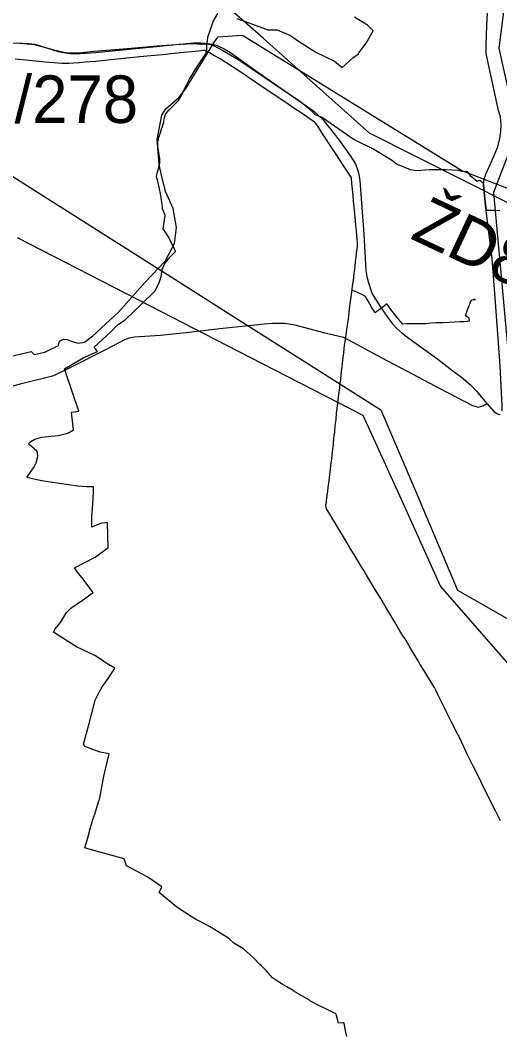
# Model space of a CAD drawing. Extents: x -789162 to -606354, y -1062736 to -945481.
# Drawn here: x -688950 to -687435, y -987160 to -983958 of the extents above; entities that cross this region are included whole.
import ezdxf

# ---------------------------------------------------------------- set-up
doc = ezdxf.new("R2010")
doc.units = 0
for name, color, linetype in [('_Hranice řešeného území', 7, 'Continuous'), ('_SIRSI VZTAHY_CYKLOTRASY MISTNI S', 7, 'Continuous'), ('_SIRSI VZTAHY_ELEKTRICKE VEDENI VN 220 kV S', 7, 'Continuous'), ('_SIRSI VZTAHY_ELEKTRICKE VEDENI VN 400 kV N', 7, 'Continuous'), ('_SIRSI VZTAHY_PRIRODNIHO PARKU', 7, 'Continuous'), ('_SIRSI VZTAHY_SILNICE I a II TRIDY_STAV POPIS', 7, 'Continuous'), ('_SIRSI VZTAHY_SILNICE II TRIDY_STAV', 7, 'Continuous'), ('_SIRSI VZTAHY_SILNICE III TRIDY_STAV', 7, 'Continuous'), ('_SIRSI VZTAHY_USES_RBK_S', 7, 'Continuous'), ('_SIRSI VZTAHY_VTL PLYNOVOD', 7, 'Continuous'), ('_SIRSI VZTAHY_ZELEZNICE NAVRH', 7, 'Continuous'), ('_SIRSI VZTAHY_ZELEZNICE_NAVRH POPIS', 7, 'Continuous')]:
    doc.layers.add(name, color=color, linetype=linetype)

msp = doc.modelspace()

# ---------------------------------------------------------------- linework, layer by layer
at = {"layer": '_Hranice řešeného území'}
for points in [[(-687918.5, -987164.8), (-687923, -987142.5), (-687926.6, -987121.8), (-687928.4, -987122), (-687932.4, -987122.4), (-687944.1, -987123.5), (-687952.2, -987095.3), (-687952.8, -987093.5), (-687982.2, -987078.9), (-688004.2, -987068), (-688032.6, -987053.2), (-688036.5, -987050.9), (-688082.3, -987023.7), (-688087.9, -987020.4), (-688108.1, -987008.6), (-688115.4, -987004.2), (-688122.5, -987000.1), (-688137.5, -986990.9), (-688146.9, -986984.3), (-688153.2, -986979.8), (-688160, -986972.1), (-688172.5, -986957.9), (-688189.3, -986941.5), (-688193, -986937.5), (-688212.3, -986918.4), (-688245.1, -986889), (-688275, -986870.6), (-688289.1, -986858.3), (-688297.7, -986851.7), (-688352.5, -986818.5), (-688363.2, -986811.5), (-688379, -986803.6), (-688396.3, -986794.8), (-688406.4, -986788.3), (-688455.2, -986756.8), (-688511.1, -986710.8), (-688502.8, -986692.7), (-688547.2, -986661.8), (-688614.6, -986626.5), (-688622, -986604), (-688736.5, -986573.3), (-688745.6, -986569.2), (-688735.9, -986537.9), (-688729.5, -986510), (-688720.2, -986480.7), (-688714.7, -986463.3), (-688702.5, -986425), (-688699.6, -986416.5), (-688699.2, -986415.4), (-688698.8, -986413.5), (-688685.7, -986343.3), (-688669.1, -986272.7), (-688697.1, -986267.5), (-688745.9, -986250.1), (-688750.5, -986242.9), (-688732.7, -986176.9), (-688715.3, -986111.7), (-688713.2, -986103.8), (-688700.3, -986078.8), (-688691, -986061.8), (-688677.4, -986042.6), (-688671.8, -986034.8), (-688666.1, -986026.3), (-688651.6, -986002.4), (-688671.3, -985990.8), (-688681.4, -985984.8), (-688686.1, -985982.1), (-688712.6, -985963.5), (-688716.6, -985961.6), (-688725.9, -985957.2), (-688732.1, -985954.2), (-688772.4, -985935.2), (-688800.7, -985917.2), (-688844.6, -985889.1), (-688839.5, -985878.8), (-688826.9, -985863.5), (-688819.4, -985853.1), (-688803.3, -985826.7), (-688790.2, -985813.6), (-688753.7, -985787.7), (-688719.7, -985763.5), (-688725.6, -985755.7), (-688726.4, -985754.6), (-688754.5, -985717.4), (-688766, -985704.3), (-688778.3, -985686.2), (-688713.1, -985652.4), (-688672.2, -985621.4), (-688674.7, -985542.8), (-688696.2, -985546.6), (-688723.4, -985557.5), (-688723.5, -985531.9), (-688723.5, -985522.5), (-688723, -985515.3), (-688720.9, -985483.1), (-688719.7, -985464.8), (-688718.5, -985447.7), (-688718.4, -985430.6), (-688739.2, -985430.7), (-688768.6, -985428.3), (-688883.2, -985411.2), (-688929.3, -985401), (-688906.1, -985367.2), (-688900, -985354.4), (-688894.2, -985334.5), (-688895.6, -985321.4), (-688898.9, -985316.6), (-688920.7, -985297.5), (-688923.7, -985294.8), (-688916.9, -985287.6), (-688903.8, -985279.6), (-688882.2, -985273.7), (-688829.7, -985268.2), (-688799.7, -985261.3), (-688781.7, -985250.9), (-688787.9, -985194.8), (-688764.5, -985191.7), (-688806.8, -985068), (-688810, -985057.6), (-688750.8, -985022.9), (-688705.5, -985003.5), (-688716.2, -984990.1), (-688663.2, -984939.8), (-688642.3, -984919.6), (-688630.9, -984912.2), (-688618, -984903.8), (-688568.4, -984855.4), (-688523.8, -984812), (-688510.7, -984785.2), (-688504.6, -984766.6), (-688501.1, -984744.8), (-688494.3, -984728), (-688479.4, -984708.2), (-688459.3, -984687.5), (-688463.5, -984677.1), (-688471.6, -984661.4), (-688475.3, -984654.1), (-688475.8, -984652.9), (-688479.2, -984645.6), (-688479.6, -984644.7), (-688486.2, -984635), (-688498.9, -984616.5), (-688494.3, -984588.2), (-688492, -984574), (-688496.2, -984562.9), (-688500.1, -984552.6), (-688501, -984546), (-688502.7, -984532.6), (-688503, -984530.6), (-688505.5, -984511.8), (-688507.1, -984504.3), (-688510, -984490.4), (-688513, -984476.6), (-688516.7, -984462), (-688518, -984456.7), (-688519.4, -984451.2), (-688516.1, -984436.7), (-688514.2, -984429.9), (-688511.1, -984418.7), (-688508.7, -984410.1), (-688508.7, -984408.6), (-688508.6, -984401.8), (-688508.6, -984395.4), (-688515.3, -984355), (-688515.4, -984342.1), (-688513.6, -984332.2), (-688512.2, -984328.2), (-688497, -984283.2), (-688493.9, -984265.9), (-688491.3, -984254.6), (-688479.9, -984241.1), (-688451.1, -984212.7), (-688441, -984195.2), (-688435.8, -984184.6), (-688426.1, -984164.7), (-688417.8, -984147.7), (-688416.6, -984145.8), (-688415.5, -984144.1), (-688397.7, -984114.8), (-688373.3, -984077.3), (-688363.9, -984063.5), (-688360.1, -984052.2), (-688360.4, -984037.6), (-688360.1, -984035.1), (-688359, -984027.4), (-688358.5, -984023.6), (-688356.9, -984011.2), (-688348.3, -983984.1), (-688340.7, -983962), (-688326, -983936.3)], [(-688266.2, -983952.3), (-688205.1, -983974.1), (-688167.7, -983987.8), (-688138, -983988.5), (-688095.7, -984005.6), (-688074.2, -984021.3), (-688016, -984058.9), (-687957.7, -984087), (-687933.1, -984107.1), (-687901.3, -984079), (-687898.8, -984076.8), (-687882.5, -984064.5), (-687880.6, -984060.8), (-687857.7, -984030.2), (-687834.8, -983991.5), (-687853.4, -983973.6), (-687894.1, -983948)]]:
    msp.add_lwpolyline(points, dxfattribs=at)
at = {"layer": '_SIRSI VZTAHY_CYKLOTRASY MISTNI S'}
msp.add_lwpolyline([(-687654.8, -981371.2), (-687432.5, -981713.4), (-687138.4, -981932.4), (-686843.2, -982326.8), (-686542.3, -982562.9), (-686470.5, -982781.9), (-686532, -983024.9), (-686928.7, -983107), (-687110, -983230.2), (-687164.7, -983298.7), (-687308.3, -983291.8), (-687308.3, -983442.4), (-687441.7, -983308.9), (-687797.3, -983504), (-687390.4, -983675.1), (-687438.3, -984046.3), (-687380.1, -984306.4), (-687455.4, -984501.5), (-687388, -985239.8)], dxfattribs=at)
at = {"layer": '_SIRSI VZTAHY_ELEKTRICKE VEDENI VN 220 kV S'}
msp.add_lwpolyline([(-689231.4, -984287.7), (-688907.4, -984492.9), (-688473, -984768.1), (-688261.6, -984902), (-688035.6, -985045.1), (-687810.4, -985187.7), (-687702.5, -985441.4), (-687568.5, -985756.3), (-687322.9, -985896.5), (-687077.4, -986036.6), (-686883.1, -986147.5), (-686512.8, -986358.6), (-686322.4, -986474.5), (-686132.5, -986576.1), (-685932.3, -986683.3), (-685866, -986596.3), (-685745.9, -986559.7)], dxfattribs=at)
at = {"layer": '_SIRSI VZTAHY_ELEKTRICKE VEDENI VN 400 kV N'}
msp.add_lwpolyline([(-688960.1, -984643.2), (-688541.2, -984858.4), (-688335.7, -984963.9), (-688108.1, -985080.8), (-687867.6, -985204.1), (-687746.8, -985469.6), (-687621.9, -985744.6), (-687434.1, -985960.1), (-687237.8, -986185.6), (-687045.1, -986407.3), (-686909.2, -986563.3), (-686634.4, -986878.4), (-686458, -987081), (-686361.4, -987300.4)], dxfattribs=at)
at = {"layer": '_SIRSI VZTAHY_PRIRODNIHO PARKU'}
msp.add_lwpolyline([(-688962.5, -984029.1), (-688928.4, -984031.9), (-688904.4, -984034.9), (-688844.2, -984051.6), (-688811.1, -984058.7), (-688797.1, -984060.4), (-688765, -984060.4), (-688717.9, -984055.6), (-688610.6, -984047.4), (-688517.4, -984039), (-688443.1, -984033.7), (-688403.1, -984031.5), (-688378, -984032.9), (-688362.9, -984032.8), (-688348.9, -984034.2), (-688330.9, -984041.6), (-688309.8, -984053.6), (-688259.7, -984083), (-688124.4, -984174.4), (-688086.2, -984199.8), (-688067.2, -984213.6), (-688040.2, -984233.8), (-688018.1, -984255.2), (-687995.1, -984264.4), (-687894.8, -984333.8), (-687832.6, -984364.7), (-687777.5, -984398.4), (-687759.5, -984412.1), (-687718.4, -984429.2), (-687697.3, -984432.1), (-687657.2, -984429.4), (-687630.1, -984429.4), (-687605.1, -984429.4), (-687566, -984431.4), (-687551.9, -984435.2), (-687538.9, -984434.4), (-687528.9, -984448.1), (-687506.9, -984465.5), (-687497.8, -984462.1), (-687487.8, -984470.6), (-687484.8, -984495.6), (-687483.8, -984513.8), (-687477.8, -984557.4), (-687453.8, -984557.4), (-687434.7, -984558.7)], dxfattribs=at)
at = {"layer": '_SIRSI VZTAHY_SILNICE II TRIDY_STAV'}
for points in [[(-689010.5, -984027.6), (-688943.1, -984030), (-688921.6, -984031.1), (-688903.9, -984033.8), (-688829.7, -984056.1), (-688807.3, -984060.4), (-688792.7, -984062.7), (-688776.6, -984064.4), (-688711, -984060.2), (-688447.2, -984033.7), (-688401.7, -984029.2), (-688379, -984028.9), (-688356.8, -984031.3), (-688339.8, -984034.2), (-688325.3, -984039), (-688306.2, -984048.5), (-688285.8, -984060.2), (-688206.5, -984116), (-688022.4, -984244.7), (-688006.2, -984259.1), (-687994.5, -984271.3), (-687968.5, -984302.2), (-687939.5, -984340.1), (-687908.4, -984383.5), (-687898.5, -984399.1), (-687891.3, -984412.3), (-687885.5, -984425.3), (-687881.3, -984439.1), (-687876.8, -984463.9), (-687864.2, -984633.2), (-687858, -984747.8), (-687855.1, -984766.9), (-687850, -984786.9), (-687837.7, -984821.1), (-687813.1, -984861.8), (-687790.1, -984895.1), (-687774.4, -984915.8), (-687762.8, -984928.8), (-687743.1, -984945.3), (-687726, -984958.7), (-687630.4, -985028), (-687583.1, -985064.3), (-687555.6, -985084.6), (-687527.1, -985108.9), (-687508.5, -985128.6), (-687476, -985167.5)], [(-687476, -985167.5), (-687453.3, -985194.2), (-687442.5, -985200.2), (-687435.3, -985202.4)]]:
    msp.add_lwpolyline(points, dxfattribs=at)
at = {"layer": '_SIRSI VZTAHY_SILNICE III TRIDY_STAV'}
for points in [[(-687427.2, -985191.8), (-687427.8, -985173.6), (-687434.4, -985048.1), (-687449.1, -984847.1), (-687459.4, -984709.9), (-687479.9, -984542.6), (-687486.6, -984478.9), (-687485.3, -984463.4), (-687479.6, -984444), (-687459.3, -984399.9), (-687441.5, -984357.3), (-687434.5, -984331), (-687431.6, -984309.4), (-687430.7, -984287.8), (-687433.1, -984262.7), (-687438.7, -984242.4), (-687468.9, -984106.9), (-687478.1, -984062.9), (-687478.4, -984036.9), (-687475.5, -983974.8), (-687471.8, -983892.9)], [(-688996.8, -985118.7), (-688950.1, -985105.6), (-688843.4, -985078.9), (-688794.2, -985054.5), (-688675.8, -984994.8), (-688619.3, -984965), (-688605.3, -984959.9), (-688589.2, -984956.8), (-688507.8, -984951.6), (-688426.1, -984942.9), (-688319.5, -984931), (-688179.8, -984916.1), (-688152.9, -984913.8), (-688114.4, -984913.8), (-688082.1, -984919.2), (-687991.7, -984943.4), (-687929, -984958.4), (-687808.2, -985023), (-687709.8, -985074.8), (-687624.2, -985120.2), (-687521.4, -985173.7), (-687502.3, -985179.3), (-687489, -985175.1), (-687476, -985167.5)]]:
    msp.add_lwpolyline(points, dxfattribs=at)
at = {"layer": '_SIRSI VZTAHY_USES_RBK_S'}
for points in [[(-686381.1, -983601.5), (-686483.4, -983793.8), (-686559.1, -983824.1), (-686556.4, -983896.2), (-686639.1, -984007.5), (-686760.1, -984040.5), (-686816.5, -984055.8), (-687051.9, -984449.1), (-687308.2, -984438.4), (-687398.9, -984492.7), (-687554.6, -984433.1), (-688247.7, -984005.7), (-688325.9, -984011.2)], [(-689000.7, -985023.4), (-688915.2, -985003.5), (-688906.1, -985013.2), (-688872.2, -985005.9), (-688828.8, -984984.6), (-688825.8, -984970.5), (-688813.2, -984964.2), (-688802.1, -984965.1), (-688786.1, -984971.4), (-688767.3, -984977), (-688746.4, -984973.8), (-688720.9, -984953.5), (-688639.4, -984879.2), (-688555.2, -984784.6), (-688492.6, -984718.1), (-688462.5, -984662.5), (-688455.9, -984612.4), (-688466.6, -984552.3), (-688491.3, -984498.1), (-688503.6, -984446.3), (-688511, -984414.1), (-688517.3, -984334.3), (-688502.2, -984257), (-688490.2, -984237.5), (-688449, -984201.5), (-688428, -984175.3), (-688338.6, -984029.4), (-688325.9, -984011.2)]]:
    msp.add_lwpolyline(points, dxfattribs=at)
at = {"layer": '_SIRSI VZTAHY_VTL PLYNOVOD'}
for points in [[(-687901.7, -984809.5), (-687901.6, -984808.8), (-687899.9, -984795.6), (-687898.6, -984786), (-687896.5, -984771), (-687896.4, -984770.2), (-687894.6, -984756.3), (-687894.2, -984752.3), (-687892.3, -984735.4), (-687890.5, -984719.7), (-687888.8, -984706.3), (-687887.2, -984693), (-687885.4, -984678.5), (-687884.6, -984672.8), (-687884.1, -984670.8), (-687884.2, -984663), (-687884.2, -984658.8), (-687885.3, -984649.1), (-687888.1, -984624.4), (-687890.2, -984603.6), (-687891.9, -984580.3), (-687893.3, -984568.3), (-687894.9, -984548.3), (-687896.8, -984529.2), (-687898.4, -984510.9), (-687900.5, -984490.8), (-687902.6, -984471.8), (-687903.5, -984458.6), (-687903.9, -984455.7), (-687904.9, -984452.6), (-687906.8, -984449.5), (-687917.2, -984434), (-687929.5, -984414.9), (-687941.3, -984397.1), (-687953.2, -984379.6), (-687963.7, -984363.5), (-687973.8, -984347.8), (-687983.8, -984333.1), (-687991.8, -984320.7), (-688001.1, -984305.8), (-688009.3, -984292.8), (-688012.2, -984288.6), (-688016.6, -984283.8), (-688017, -984283.3), (-688017.5, -984282.9), (-688020.6, -984279.8), (-688027.7, -984274.1), (-688041, -984264.8), (-688062, -984250.6), (-688082.5, -984237.2), (-688103.7, -984222.5), (-688124, -984209.1), (-688144.8, -984194.9), (-688167.7, -984179.8), (-688191.8, -984163.4), (-688203.3, -984155.6), (-688221, -984143.6), (-688229.5, -984137.4), (-688236.4, -984133), (-688246.5, -984125.8), (-688267.6, -984112.3), (-688279, -984104.8), (-688300.9, -984090.9), (-688318.4, -984080.1), (-688335.9, -984069.9), (-688351.6, -984060.9), (-688359.6, -984056.2), (-688367.5, -984053.4), (-688370.7, -984053.4), (-688378.7, -984053.9), (-688387.3, -984055.1), (-688409.4, -984057.3), (-688434, -984060), (-688472.6, -984064.1), (-688500.6, -984066.7), (-688537.5, -984070.2), (-688572.6, -984073.3), (-688601.2, -984076.4), (-688613.4, -984077.7), (-688621.5, -984078.8), (-688642.7, -984080.8), (-688655.3, -984082.2), (-688682.6, -984084.7), (-688711.5, -984087.6), (-688730, -984088.9), (-688743.6, -984090.1), (-688763.7, -984091.8), (-688796.1, -984094.3), (-688818, -984093.9), (-688843.5, -984092.4), (-688872.5, -984089.8), (-688900.9, -984087.2), (-688932.3, -984083.8), (-688965.9, -984080.3)], [(-687432.5, -986484.7), (-687436.8, -986475.6), (-687448.6, -986453.1), (-687458.8, -986433), (-687471.1, -986408.3), (-687483.1, -986384.1), (-687492.6, -986364.6), (-687505.6, -986338.1), (-687517.7, -986314.3), (-687529.2, -986290.8), (-687538.7, -986271.5), (-687548.6, -986251.3), (-687556.5, -986235.1), (-687559.5, -986227.8), (-687563.5, -986220.4), (-687564.8, -986216.1), (-687567.3, -986212.8), (-687575.1, -986197), (-687588.4, -986171.1), (-687600.8, -986145.4), (-687609.4, -986127.8), (-687621.6, -986104.4), (-687629.5, -986087.5), (-687637.3, -986071.9), (-687641.4, -986063.7), (-687646.3, -986055.7), (-687651.7, -986046.9), (-687665.5, -986024.3), (-687675, -986009), (-687686.1, -985991.2), (-687694.9, -985976.5), (-687705.7, -985958.4), (-687716.7, -985939.8), (-687725.9, -985924.8), (-687734.5, -985910.4), (-687739.4, -985903.4), (-687750.5, -985884.6), (-687766.7, -985857.6), (-687782.9, -985830.9), (-687794, -985812.2), (-687811.3, -985783.2), (-687828.1, -985756.1), (-687843.5, -985730.2), (-687849.8, -985719.5), (-687860.2, -985701.9), (-687865, -985694.2), (-687873.9, -985679.9), (-687884.2, -985662.3), (-687895.4, -985643.5), (-687908.5, -985622.5), (-687918.3, -985606), (-687929, -985587.8), (-687940.6, -985569), (-687950.1, -985553), (-687957.6, -985540.7), (-687964.7, -985529), (-687972, -985516.9), (-687975.4, -985511.6), (-687977.9, -985506.6), (-687982.2, -985499.6), (-687983.8, -985494.8), (-687984.2, -985486.9), (-687983, -985479.6), (-687982.5, -985475), (-687981.2, -985465), (-687980.2, -985458.1), (-687978.4, -985444.3), (-687978.3, -985443.5), (-687977, -985432.4), (-687974.3, -985411.1), (-687971.6, -985391.6), (-687969.8, -985375.5), (-687968.3, -985362.1), (-687965.5, -985341.8), (-687963.3, -985318.5), (-687961.9, -985305.9), (-687960.6, -985294.9), (-687958.8, -985277.3), (-687956.5, -985257), (-687954.7, -985237.9), (-687952.3, -985218), (-687950.6, -985197), (-687947.7, -985174.9), (-687945.4, -985156.9), (-687943.5, -985138.8), (-687940.8, -985118.4), (-687939.9, -985110.1), (-687938.8, -985103.3), (-687937.5, -985092.4), (-687935.7, -985074.4), (-687933.5, -985051.5), (-687930.8, -985030.7), (-687927.9, -985007.9), (-687925.3, -984983.8), (-687922.6, -984966.1), (-687921.4, -984959.4), (-687920.4, -984950), (-687920.3, -984949), (-687920, -984946.4), (-687919.7, -984943.9), (-687919.6, -984943), (-687918.3, -984933.9), (-687918.3, -984933.3), (-687916.3, -984920.4), (-687914.4, -984907.2), (-687912.2, -984892), (-687910.6, -984878.7), (-687908.3, -984860.7), (-687905.2, -984837.8), (-687902.7, -984816.5), (-687901.9, -984811), (-687901.9, -984810.4)], [(-687901.9, -984810.4), (-687901.7, -984809.5)], [(-687901.9, -984810.4), (-687901.5, -984810.4), (-687901.1, -984810.4), (-687900.5, -984810.5), (-687900.4, -984809.7)], [(-687900.4, -984809.7), (-687900.9, -984809.6), (-687901.7, -984809.5)], [(-687900.4, -984809.7), (-687900.3, -984809.7), (-687898.4, -984810.6), (-687887.9, -984815.2), (-687873.6, -984821.7), (-687866.3, -984825.5), (-687862.7, -984827.5), (-687861.5, -984828.1), (-687856.8, -984835.5), (-687848, -984850.7), (-687838.8, -984866.3), (-687830.3, -984880.6), (-687829.5, -984880.9), (-687828.8, -984880.4), (-687823.6, -984876.2), (-687817.5, -984871.8), (-687814.9, -984869.8), (-687812.3, -984867.9), (-687806.9, -984864.1), (-687804.9, -984862.5), (-687804.6, -984862.3), (-687792.9, -984853.4), (-687792.3, -984853.4), (-687791.6, -984854.1), (-687788.3, -984858.6), (-687779.9, -984870.3), (-687764.4, -984890.5), (-687754.8, -984902.1), (-687744.5, -984915.3), (-687743, -984915.7), (-687741.4, -984915.6), (-687728.8, -984915.3), (-687712.8, -984915.1), (-687695.2, -984914.9), (-687676.2, -984914.7), (-687668.9, -984914.7), (-687652.4, -984912.8), (-687635.6, -984911.8), (-687615.3, -984911.4), (-687595.1, -984910.8), (-687577.5, -984909.8), (-687561.3, -984908.9), (-687549.3, -984908.4), (-687537.4, -984907.4), (-687535.1, -984907.3), (-687530.9, -984906.6), (-687530.9, -984906.6), (-687530.9, -984905.3), (-687531, -984905.1), (-687531.5, -984898.1), (-687543.6, -984890.6), (-687535.8, -984869.1), (-687528.6, -984850.4), (-687528.5, -984850.2), (-687524.9, -984840.2), (-687518.9, -984839.5), (-687516.4, -984839.3), (-687515.1, -984839.1), (-687514.8, -984839.1), (-687514.6, -984839.1)], [(-687514.2, -984839), (-687514.2, -984838.6), (-687514.4, -984838.6), (-687514.6, -984838.6), (-687514.7, -984838.6), (-687514.6, -984839.1)], [(-687514.6, -984839.1), (-687514.4, -984839.1), (-687514.2, -984839)], [(-687514.2, -984839), (-687514, -984839), (-687513.6, -984839), (-687513.1, -984838.9), (-687513, -984838.9), (-687512.9, -984838.9), (-687512.7, -984838.9), (-687512.3, -984838.9)]]:
    msp.add_lwpolyline(points, dxfattribs=at)
at = {"layer": '_SIRSI VZTAHY_ZELEZNICE NAVRH'}
msp.add_lwpolyline([(-686795.8, -991462.7), (-686725.1, -990794.1), (-686770.6, -989950.2), (-686813.7, -988842.7), (-686780.8, -988439.8), (-686796, -987844.3), (-686704.8, -987423.6), (-686618.7, -987223.4), (-686441.4, -986992.8), (-686276.8, -986729.2), (-686099.6, -986105.8), (-686097, -985900.5), (-686150.2, -985761.2), (-686352.8, -985497.6), (-686628.8, -985211.2), (-686940.3, -984826), (-687246.7, -984615.7), (-687846.9, -984314.1), (-688181.2, -984015.1), (-688416.7, -983809.8), (-688553.5, -983657.8), (-688738.3, -983432.2)], dxfattribs=at)

# ---------------------------------------------------------------- texts
at = {"layer": '_SIRSI VZTAHY_SILNICE I a II TRIDY_STAV POPIS'}
msp.add_text('II/278', height=150, dxfattribs=at).set_placement((-689079.4, -984282.1))
at = {"layer": '_SIRSI VZTAHY_ZELEZNICE_NAVRH POPIS'}
msp.add_text('ŽD8_D26D', height=150, rotation=334.8581, dxfattribs=at).set_placement((-687721.6, -984645.4))

doc.saveas('drawing.dxf')
